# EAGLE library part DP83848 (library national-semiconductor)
PHYTER® - Extended Temperature Single Port 10/100 Mb/s Ethernet Physical Layer Transceiver Auto generated by make-symbol-device-package-bsdl.ulp Rev. 34 Source: dp83848yb.bsdl http://www.national.com/ds/DP/DP83848VYB.pdf
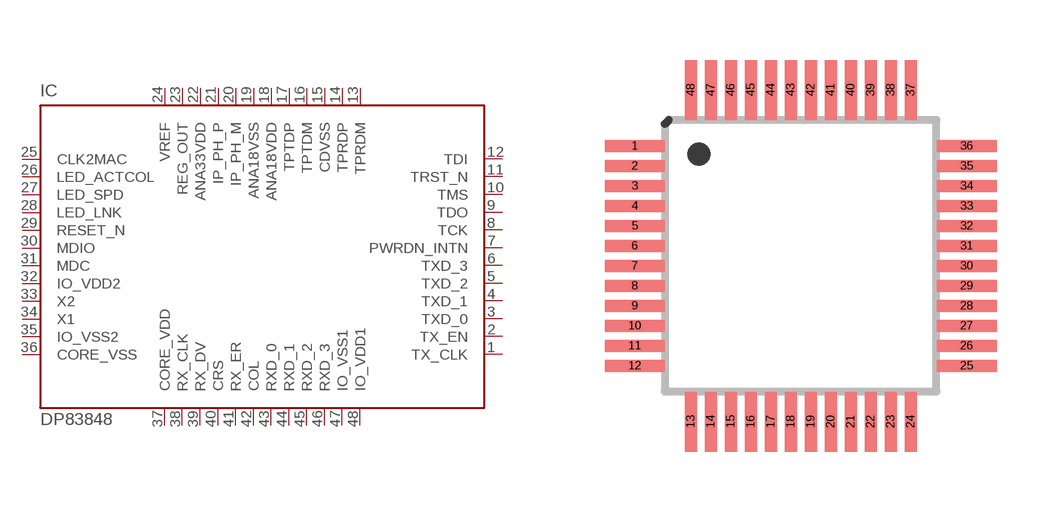
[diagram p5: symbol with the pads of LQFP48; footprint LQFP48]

Designator prefix IC

## DP83848 (MPN: DP83848VYB; OC_FARNELL: 1286817; OC_NEWARK: 11N4484)  [LQFP48]
1  TX_CLK
2  TX_EN
3  TXD_0
4  TXD_1
5  TXD_2
6  TXD_3
7  PWRDN_INTN
8  TCK  in
9  TDO  out
10  TMS  in
11  TRST_N  in
12  TDI  in
13  TPRDM
14  TPRDP
15  CDVSS  pwr
16  TPTDM
17  TPTDP
18  ANA18VDD  pwr
19  ANA18VSS  pwr
20  IP_PH_M  in
21  IP_PH_P  in
22  ANA33VDD  pwr
23  REG_OUT  out
24  VREF
25  CLK2MAC
26  LED_ACTCOL
27  LED_SPD
28  LED_LNK
29  RESET_N  in
30  MDIO
31  MDC  in
32  IO_VDD2  pwr
33  X2  out
34  X1  in
35  IO_VSS2  pwr
36  CORE_VSS  pwr
37  CORE_VDD  pwr
38  RX_CLK
39  RX_DV
40  CRS
41  RX_ER
42  COL
43  RXD_0
44  RXD_1
45  RXD_2
46  RXD_3
47  IO_VSS1  pwr
48  IO_VDD1  pwr

## Footprint LQFP48 (pad centres in mm)
LQFP48 VXH48A Auto generated by make-symbol-device-package-bsdl.ulp Rev. 34 Source: http://www.national.com/ds/DP/DP83848VYB.pdf
smd 1.5 x 0.3: 1 -4.15,2.75; 2 -4.15,2.25; 3 -4.15,1.75; 4 -4.15,1.25; 5 -4.15,0.75; 6 -4.15,0.25; 7 -4.15,-0.25; 8 -4.15,-0.75; 9 -4.15,-1.25; 10 -4.15,-1.75; 11 -4.15,-2.25; 12 -4.15,-2.75; 25 4.15,-2.75; 26 4.15,-2.25; 27 4.15,-1.75; 28 4.15,-1.25; 29 4.15,-0.75; 30 4.15,-0.25; 31 4.15,0.25; 32 4.15,0.75; 33 4.15,1.25; 34 4.15,1.75; 35 4.15,2.25; 36 4.15,2.75
smd 0.3 x 1.5: 13 -2.75,-4.15; 14 -2.25,-4.15; 15 -1.75,-4.15; 16 -1.25,-4.15; 17 -0.75,-4.15; 18 -0.25,-4.15; 19 0.25,-4.15; 20 0.75,-4.15; 21 1.25,-4.15; 22 1.75,-4.15; 23 2.25,-4.15; 24 2.75,-4.15; 37 2.75,4.15; 38 2.25,4.15; 39 1.75,4.15; 40 1.25,4.15; 41 0.75,4.15; 42 0.25,4.15; 43 -0.25,4.15; 44 -0.75,4.15; 45 -1.25,4.15; 46 -1.75,4.15; 47 -2.25,4.15; 48 -2.75,4.15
